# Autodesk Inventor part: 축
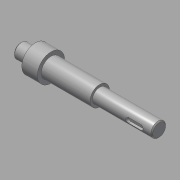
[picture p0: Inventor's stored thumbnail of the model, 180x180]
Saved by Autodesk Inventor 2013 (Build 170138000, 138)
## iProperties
Created: 2015-09
Part Number: 축
Material: 강철, 연강
Document SubType Name: Modeling
Designer: mduedu
Density: 7.86 g/cm^3
Mass: 263.424 g
Surface Area: 86.4309 cm^2
Volume: 33.5145 cm^3
Author: mduedu
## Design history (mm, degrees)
sketch "스케치1"
  geometry: L1 (-71, 0)-(71, 0); L2 (-71, 0)-(-71, 7.5); L3 (-71, 7.5)-(-56, 7.5); L4 (-56, 7.5)-(-56, 14); L5 (-56, 14)-(-40, 14); L6 (-40, 14)-(-40, 10); L7 (-40, 10)-(10, 10); L8 (10, 10)-(10, 7.5); L9 (10, 7.5)-(71, 7.5); L10 (71, 7.5)-(71, 0); 2 further points
  constraints: 20 end point, 5 parallel, 2 horizontal, 2 perpendicular, 1 coincident, 1 midpoint, 1 vertical
  dimensions: "d0" = 142 distance of L1.start L1.end; "d2" = 16 distance of L4.end L5.end; "d3" = 50 distance of L6.end L7.end; "d5" = 15 diameter of L3 L1; "d6" = 15 diameter of L9 L1; "d7" = 20 diameter of L7 L1; "d8" = 28 diameter of L5 L1; "d31" = 15 distance of L2.end L3.end
revolve "회전1" sketch "스케치1" stored, may be unused: angle "d9" = 90 deg
node "작업 평면1"
sketch "스케치2"
  geometry: L1 (6, 2.5)-(19, 2.5); L2 (19, -2.5)-(6, -2.5); L3 (6, 2.5)-(19, -2.5); L4 (19, 2.5)-(6, -2.5); L5 (30.5, -7.5)-(30.5, 7.5) reference; A1 r 2.5 centre (6, 0) between (6, 2.5) and (6, -2.5); A2 r 2.5 centre (19, 0) between (19, -2.5) and (19, 2.5); 2 further points
  constraints: 8 end point, 4 point on circle, 4 tangent, 2 centre point, 2 midpoint, 1 horizontal, 1 horizontal alignment, 1 parallel
  dimensions: "d10" = 18 dimension on A2 A1; "d12" = 9 distance edge to line of A2 L5; "d13" = 5 distance between parallel lines of L2 L1
extrude "돌출1" cut sketch "스케치2" distance "d14" = 3; taper "d15" = 0 deg
node "작업 평면2"
sketch "스케치4"
  geometry: L1 (3, -3)-(-13, -3); L2 (-13, 3)-(3, 3); L3 (-25, 10)-(-25, -10) reference; A1 r 3 centre (-13, 0) between (-13, 3) and (-13, -3); A2 r 3 centre (3, 0) between (3, -3) and (3, 3); 1 further point
  constraints: 4 end point, 4 point on circle, 4 tangent, 2 centre point, 1 horizontal, 1 horizontal alignment, 1 parallel
  dimensions: "d16" = 22 dimension on A1 A2; "d18" = 6 distance between parallel lines of L2 L1; "d19" = 9 distance edge to line of A1 L3
extrude "돌출2" cut sketch "스케치4" distance "d20" = 3.5; taper "d21" = 0 deg
sketch "스케치5"
  geometry: L1 (10, 7.5)-(71, 7.5) reference; L2 (10, -7.5)-(71, -7.5) reference; L3 (45, 7.5)-(45, -7.5); L4 (45, -5.5)-(43, -7.5); L5 (45, -7.5)-(43, -7.5); L6 (45, -7.5)-(45, -5.5); L7 (10, -10)-(10, 10) reference; 1 further point
  constraints: 8 end point, 4 point on line, 1 collinear, 1 perpendicular
  dimensions: "d22" = 4 diameter of L4.end L3; "d24" = 45 deg angle of L3 L4; "d26" = 35 distance between parallel lines of L3 L7
revolve "회전2" sketch "스케치5" stored, may be unused: angle "d27" = 90 deg
chamfer "모따기1" distance "d28" = 1; stored, may be unused: second distance "d29" = 2, angle "d30" = 45 deg
sketch "스케치6"
  geometry: L1 (45, -5.5)-(43, -7.5) reference; L2 (45, -5.5)-(47, -7.5) reference; 2 further points
  constraints: 1 coincident
node "솔리드1"
